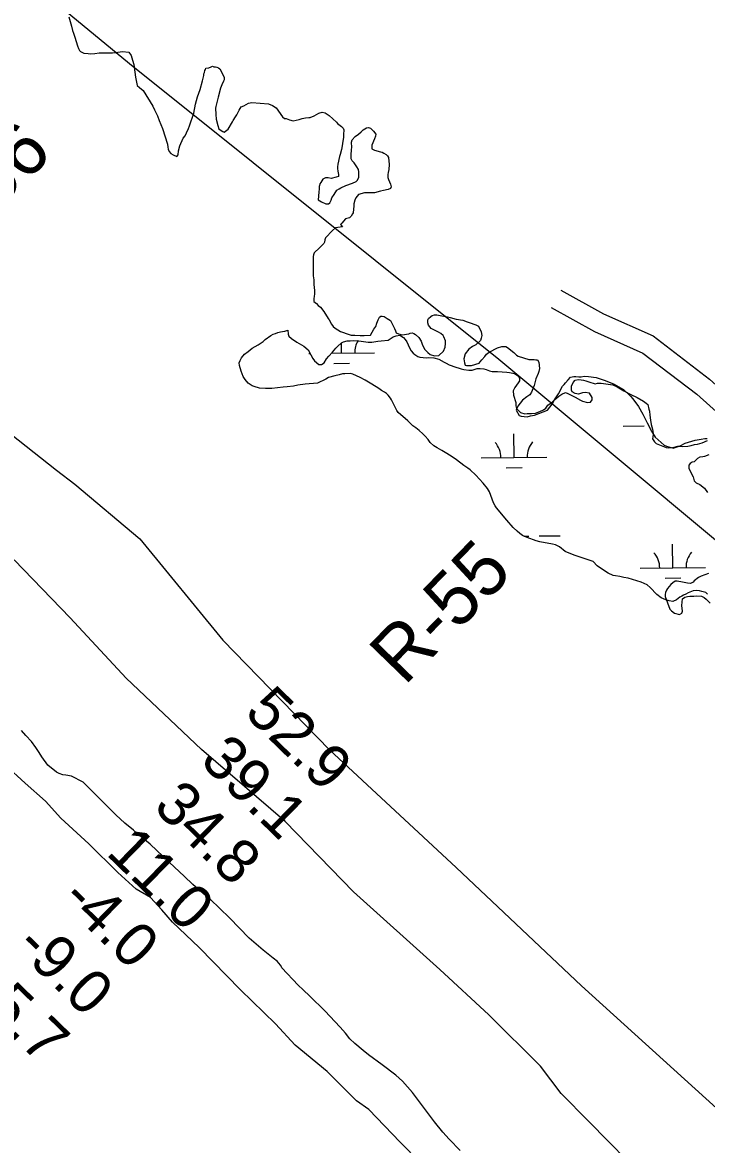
# Model space of a CAD drawing. Extents: x 3146026 to 3183936, y 897894 to 923344.
# Drawn here: x 3172319 to 3173362, y 912205 to 913917 of the extents above; entities that cross this region are included whole.
import ezdxf

# ---------------------------------------------------------------- set-up
doc = ezdxf.new("R2010")
doc.units = 0
for name, color, linetype in [('V-LEVE-TOET', 7, 'Continuous'), ('V-RIVR-EDGE', 7, 'Continuous'), ('V-RIVR-RANG', 7, 'Continuous'), ('V-RIVR-RANG-IDEN', 7, 'Continuous'), ('V-ROAD-CNTR', 7, 'Continuous'), ('V-SITE-VEGE', 7, 'Continuous'), ('V-TOPO-BNDY', 7, 'Continuous'), ('V-WETL-SWMP', 7, 'Continuous')]:
    doc.layers.add(name, color=color, linetype=linetype)

msp = doc.modelspace()

# ---------------------------------------------------------------- linework, layer by layer
at = {"layer": 'V-LEVE-TOET'}
for points in [[(3172100.1, 913448.3), (3172370.8, 913233.9), (3172398.7, 913212.6), (3172497.8, 913129.1), (3172624.4, 912974.6), (3172787.3, 912807.3), (3172980.7, 912627.4), (3173171.4, 912446.8), (3173377.7, 912260.1), (3173591.1, 912050.9), (3173767.1, 911895.3), (3173843.3, 911824.3), (3173892.6, 911768.4), (3173997.2, 911662.3), (3174154.9, 911518.6), (3174255.5, 911433.9), (3174348.6, 911370.2), (3174431.4, 911311.7), (3174516, 911243.3)], [(3173271.6, 912149.5), (3173183, 912239.6), (3173140.6, 912282.5), (3173109, 912324.3), (3173030.1, 912402.6), (3172955.5, 912472), (3172824.1, 912590.2), (3172719.5, 912697.6), (3172592.1, 912807.5), (3172477.4, 912916.6), (3172391.5, 913008.7), (3172306.5, 913097.3)]]:
    msp.add_lwpolyline(points, dxfattribs=at)
at = {"layer": 'V-RIVR-EDGE'}
msp.add_lwpolyline([(3172955.3, 912146.9), (3172895, 912208.4), (3172847.5, 912258), (3172828.6, 912271.4), (3172783.5, 912315.9), (3172735.1, 912356.2), (3172704.7, 912389), (3172651.7, 912440.9), (3172588.6, 912505.3), (3172548, 912544.2), (3172531.4, 912562.7), (3172514.4, 912581.6), (3172492.3, 912594.6), (3172464.6, 912620.1), (3172420.4, 912663.6), (3172377.5, 912703), (3172354, 912728.5), (3172323.1, 912756.2), (3172293.2, 912783.6)], dxfattribs=at)
at = {"layer": 'V-ROAD-CNTR'}
for points in [[(3173139.9, 913508.6), (3173205.1, 913472.4), (3173280.7, 913438.7), (3173366.6, 913372.9), (3173416.8, 913328), (3173469.6, 913282.3), (3173498.8, 913242.4), (3173574.6, 913161), (3173657.4, 913103.1), (3173709, 913080.7), (3173781.9, 913041.6), (3173863.9, 912987.1), (3173918.4, 912931.4), (3173981.3, 912871.8), (3174036.9, 912823), (3174086.6, 912783.4), (3174169.8, 912735.6), (3174248.5, 912696.9), (3174316.5, 912653.2), (3174389.2, 912593.3), (3174464.7, 912522.1), (3174535.7, 912475.2)], [(3173125.3, 913482.4), (3173191.7, 913445.6), (3173265.2, 913412.7), (3173347.4, 913349.8), (3173397, 913305.4), (3173447.4, 913261.8), (3173475.7, 913223.2), (3173554.8, 913138.2), (3173642.7, 913076.8), (3173695.9, 913053.6), (3173766.5, 913015.8), (3173844.7, 912963.9), (3173897.4, 912910), (3173961, 912849.6), (3174017.7, 912800), (3174069.7, 912758.5), (3174155.7, 912709.2), (3174233.7, 912670.7)]]:
    msp.add_lwpolyline(points, dxfattribs=at)
at = {"layer": 'V-SITE-VEGE'}
for points in [[(3172389.6, 913925.7), (3172392.8, 913915.2), (3172393.6, 913911.3), (3172395.5, 913905), (3172396.7, 913901.1), (3172399.1, 913894.9), (3172401, 913887.9), (3172403, 913881.6), (3172404.5, 913877.3), (3172406.1, 913874.6), (3172407.7, 913873), (3172412.4, 913870.3), (3172419, 913869.9), (3172422.9, 913869.5), (3172429.6, 913869.9), (3172436.2, 913871.1), (3172452.2, 913871.1), (3172456.5, 913870.8), (3172460.8, 913871.2), (3172468.2, 913872.3), (3172471.8, 913873.1), (3172481.1, 913872), (3172484.7, 913866.9), (3172487, 913859.9), (3172488.6, 913852.8), (3172490.6, 913841.5), (3172491.4, 913833.7), (3172493.7, 913821.2), (3172497.6, 913817.7), (3172503.1, 913813.4), (3172518, 913789.6), (3172520.4, 913783.8), (3172524.7, 913774.8), (3172527.4, 913767.4), (3172532.5, 913755.6), (3172540.4, 913731.4), (3172540.8, 913726.7), (3172541.2, 913724), (3172542.7, 913720.1), (3172545.5, 913717.4), (3172548.6, 913715.4), (3172554.5, 913712.7), (3172556.4, 913715.4), (3172556.8, 913721.3), (3172559.1, 913729.1), (3172564.2, 913740.5), (3172566.9, 913744.4), (3172569.2, 913748.7), (3172572, 913755.3), (3172573.9, 913759.6), (3172580.5, 913778.8), (3172582.8, 913792.5), (3172584.4, 913798.3), (3172586, 913803.8), (3172590.2, 913815.1), (3172593.7, 913828), (3172595.7, 913836.2), (3172595.7, 913839), (3172596.4, 913840.9), (3172597.2, 913843.7), (3172598, 913845.6), (3172598.8, 913847.2), (3172603.1, 913848), (3172607, 913849.5), (3172608.9, 913850.3), (3172610.9, 913849.5), (3172613.2, 913849.5), (3172615.6, 913849.2), (3172617.9, 913848), (3172619.9, 913846.4), (3172626.5, 913833.9), (3172626.5, 913829.6), (3172625.8, 913827.7), (3172623, 913822.2), (3172621.1, 913816.7), (3172617.6, 913803.1), (3172613.7, 913789), (3172613.3, 913786.3), (3172613.7, 913776.9), (3172614.5, 913769.5), (3172616.9, 913760.1), (3172618.5, 913755), (3172620.4, 913753.1), (3172624.7, 913750.7), (3172626.7, 913749.9), (3172632.9, 913754.6), (3172639.5, 913765.6), (3172640.3, 913767.6), (3172643.8, 913773.4)], [(3172643.8, 913773.4), (3172645.8, 913776.2), (3172649.3, 913783.6), (3172652.4, 913788.3), (3172656.7, 913790.2), (3172663.7, 913793.8), (3172668.8, 913794.9), (3172694.2, 913793), (3172700.1, 913790.3), (3172705.9, 913786.8), (3172715.7, 913773.2), (3172718.8, 913770.8), (3172721.2, 913770.4), (3172726.3, 913768.5), (3172731.7, 913767.3), (3172741.1, 913768.9), (3172745.4, 913770.5), (3172750.5, 913771.6), (3172755.6, 913772.4), (3172757.9, 913772.4), (3172763.8, 913774.8), (3172770.8, 913778.7), (3172775.9, 913780.3), (3172780.6, 913779.1), (3172786.8, 913775.2), (3172798.2, 913765.1), (3172799.7, 913763.1), (3172801.3, 913761.6), (3172805.6, 913758.5), (3172808.3, 913755.7), (3172809.1, 913753.4), (3172808.7, 913746.4), (3172808.7, 913741.7), (3172807.6, 913735.8), (3172806.8, 913728.8), (3172805.7, 913723.3), (3172803.7, 913715.9), (3172802.5, 913712.4), (3172799.8, 913701), (3172799.4, 913696.7), (3172799.5, 913694.4), (3172800.2, 913690.5), (3172801, 913685), (3172801, 913682.3), (3172797.5, 913681.1), (3172789.7, 913679.1), (3172785, 913679.9), (3172781.1, 913679.9), (3172777.2, 913677.9), (3172774.1, 913672.8), (3172772.5, 913670.9), (3172772.2, 913668.5), (3172771.4, 913666.6), (3172771.4, 913663.5), (3172771, 913658), (3172769.8, 913646.3), (3172774.9, 913643.2), (3172781.6, 913640.4), (3172785.9, 913640.4), (3172787.8, 913642), (3172789.8, 913645.9), (3172790.9, 913649.4), (3172794.4, 913654.5), (3172798.3, 913661.2), (3172801.9, 913663.5), (3172804.6, 913664.7), (3172812.4, 913668.6), (3172822.5, 913672.1), (3172828, 913674.5), (3172829.6, 913676.1), (3172831.9, 913680.4), (3172831.9, 913689.4), (3172831.5, 913692.9), (3172829.1, 913696.8), (3172824.8, 913703), (3172821.7, 913706.1), (3172820.5, 913709.3), (3172820.5, 913717.1), (3172820.9, 913721), (3172820.9, 913723.3), (3172821.3, 913726.5), (3172820.9, 913734.3), (3172821.6, 913738.2), (3172826.3, 913743.3), (3172831.4, 913746.8), (3172835.7, 913750.3), (3172838.4, 913753.4), (3172843.9, 913756.6), (3172846.6, 913757), (3172849.7, 913755.8), (3172854.4, 913751.5), (3172858, 913746.8), (3172857.6, 913743.7), (3172856, 913739.8), (3172851.7, 913730), (3172851.8, 913724.5), (3172855.7, 913722.2), (3172865, 913719.9), (3172867.4, 913719.1), (3172870.1, 913717.9), (3172873.6, 913715.6)], [(3172873.6, 913715.6), (3172875.6, 913713.7), (3172877.2, 913710.9), (3172878.4, 913700.4), (3172877.6, 913692.9), (3172876.8, 913688.3), (3172876, 913685.1), (3172876.4, 913680.8), (3172877.2, 913677.7), (3172880.4, 913670.3), (3172881.5, 913666.4), (3172880.4, 913663.7), (3172876.9, 913662.5), (3172869.8, 913660.5), (3172865.1, 913659.7), (3172855.8, 913657.4), (3172840.9, 913657.3), (3172831.6, 913654.6), (3172827.3, 913649.5), (3172825.7, 913646), (3172824.5, 913640.5), (3172824.6, 913637.4), (3172823.4, 913626.8), (3172822.6, 913624.9), (3172820.3, 913621.4), (3172817.9, 913619), (3172813.6, 913618.2), (3172811.7, 913617.4), (3172806.2, 913610.8), (3172804.3, 913608.8), (3172807.3, 913605.5), (3172796.5, 913603.7), (3172791.8, 913599.8), (3172781.3, 913588.5), (3172780.1, 913585.7), (3172779.7, 913581.8), (3172778.6, 913579.9), (3172771.9, 913573.2), (3172763.7, 913565.4), (3172763, 913562.7), (3172762.6, 913559.9), (3172762.6, 913530.6), (3172763.4, 913524.4), (3172763.4, 913517.3), (3172764.6, 913508), (3172764.6, 913502.1), (3172763.8, 913500.1), (3172763.5, 913494.7), (3172763.5, 913491.2), (3172767.4, 913488.4), (3172770.1, 913485.3), (3172773.3, 913482.6), (3172778.7, 913476), (3172785, 913465.4), (3172786.6, 913463.1), (3172790.1, 913456.8), (3172792.8, 913453.3), (3172796, 913450.6), (3172803.8, 913445.5), (3172817.1, 913440.9), (3172820.2, 913440.1), (3172826.1, 913440.1), (3172834.3, 913439.3), (3172840.1, 913439.3), (3172849.9, 913440.1), (3172855, 913449.1), (3172857.7, 913453.4), (3172859.6, 913458.1), (3172861.6, 913463.6), (3172863.5, 913467.5), (3172865.5, 913468.7), (3172867.8, 913468.7), (3172870.6, 913468.3), (3172875.2, 913465.6), (3172880.3, 913462.1), (3172886.6, 913450), (3172887.8, 913446.4), (3172889, 913443.7), (3172892.5, 913441.8), (3172898, 913440.6), (3172908.1, 913441.8), (3172910.5, 913443), (3172913.2, 913443.4), (3172915.9, 913442.6), (3172918.3, 913441), (3172923.7, 913436.4), (3172926.9, 913430.9), (3172928.8, 913426.2), (3172929.6, 913423.5), (3172932.8, 913418), (3172937.1, 913413.3), (3172940.6, 913410.2), (3172947.2, 913408.3), (3172953.9, 913409.1), (3172960.9, 913415.3), (3172963.6, 913421.6), (3172964.4, 913427.4), (3172964.4, 913431.3), (3172961.6, 913437.6), (3172960.5, 913439.5), (3172956.9, 913442.3)], [(3172956.9, 913442.3), (3172953.4, 913444.6), (3172942.1, 913450.1), (3172938.2, 913455.1), (3172937, 913459), (3172937.4, 913463.3), (3172938.5, 913465.3), (3172941.7, 913468.4), (3172944, 913470), (3172947.5, 913471.2), (3172951, 913471.2), (3172958.8, 913469.2), (3172967.4, 913468.1), (3172971.4, 913466.9), (3172980.7, 913464.6), (3172990.5, 913462.6), (3172997.2, 913460.3), (3173000.3, 913459.5), (3173010.4, 913455.6), (3173014.7, 913453.7), (3173018.7, 913445.1), (3173019.5, 913439.3), (3173018.7, 913435.3), (3173017.5, 913431.8), (3173010.5, 913425.2), (3173005.4, 913422.4), (3173000, 913418.5), (3172994.1, 913411.5), (3172992.2, 913403.7), (3172993, 913397.8), (3172994.1, 913394.3), (3172996.1, 913393.5), (3173003.9, 913393.5), (3173015.6, 913397.4), (3173017.2, 913399), (3173019.5, 913402.1), (3173024.2, 913407.6), (3173026.9, 913411.1), (3173030.8, 913413.9), (3173043.7, 913420.5), (3173050.3, 913422.5), (3173056.2, 913422.5), (3173058.9, 913421), (3173068.3, 913413.6), (3173072.6, 913409.3), (3173075, 913408.1), (3173083.2, 913405.4), (3173091.4, 913403), (3173099.6, 913402.7), (3173102, 913402.3), (3173104.3, 913402.3), (3173106.6, 913398.8), (3173107.4, 913389), (3173106.7, 913384.7), (3173105.5, 913381.2), (3173102, 913373.4), (3173099.3, 913363.2), (3173095.4, 913353), (3173092.7, 913348.7), (3173088, 913346), (3173081.4, 913340.9), (3173074.7, 913331.5), (3173072, 913325.3), (3173076.3, 913317.1), (3173079.4, 913316.3), (3173088.8, 913315.5), (3173093.9, 913316.7), (3173100.1, 913317.9), (3173106.8, 913320.2), (3173119.7, 913325.3), (3173126.7, 913334.7), (3173130.6, 913341.4), (3173136.4, 913350.4), (3173142.7, 913362.1), (3173145, 913364.8), (3173147.3, 913367.2), (3173151.2, 913371.9), (3173154.7, 913375.8), (3173159.8, 913377), (3173162.9, 913377), (3173167.6, 913376.2), (3173171.1, 913376.6), (3173175.8, 913377.4), (3173182.1, 913377), (3173193.8, 913375.5), (3173207.5, 913370.8), (3173221.2, 913365.4), (3173235.6, 913356.8), (3173246.2, 913346.7), (3173249.7, 913342.8), (3173258.4, 913331.1), (3173265, 913319.3), (3173271.7, 913306.1), (3173278.3, 913293.6), (3173283.8, 913284.2), (3173297.9, 913272.1), (3173301.4, 913270.6), (3173312, 913267.5), (3173314.7, 913268.3), (3173322.1, 913271), (3173329.9, 913274.9)], [(3173329.9, 913274.9), (3173345.2, 913279.6), (3173354.2, 913281.2), (3173359.6, 913282), (3173363.5, 913282)], [(3173365.9, 913257.4), (3173359.3, 913255), (3173356.5, 913254.3), (3173352.2, 913253.5), (3173348.7, 913251.5), (3173343.3, 913246.8), (3173340.5, 913246), (3173337.4, 913244.1), (3173335.1, 913241.3), (3173335.5, 913237), (3173338.2, 913230.4), (3173341.7, 913223.8), (3173342.5, 913221.8), (3173343.7, 913217.5), (3173346.5, 913214.8), (3173351.9, 913212.1), (3173359.4, 913206.6), (3173363.7, 913200)], [(3173365.4, 913076.1), (3173354.1, 913072.2), (3173350.2, 913070.2), (3173343.6, 913064.8), (3173342, 913062.8), (3173338.1, 913060.8), (3173333.4, 913061.2), (3173325.6, 913063.2), (3173317.4, 913064.7), (3173314.7, 913064.7), (3173310.8, 913062), (3173308, 913059.6), (3173302.6, 913053.4), (3173301.4, 913051), (3173299.9, 913047.1), (3173299.1, 913044), (3173299.1, 913041.2), (3173306.5, 913021.7), (3173308.9, 913019), (3173313.6, 913015.5), (3173321, 913013.5), (3173324.9, 913015.5), (3173325.7, 913018.6), (3173324.9, 913027.2), (3173325.7, 913037.4), (3173329.2, 913040.1), (3173333.1, 913041.3), (3173336.6, 913041.7), (3173342.8, 913041.7), (3173347.1, 913042.1), (3173354.6, 913041.7), (3173358.5, 913039.8), (3173361.6, 913037), (3173367.9, 913030.8)], [(3172746.9, 912440.6), (3172739.5, 912448), (3172714.8, 912474.5), (3172712.9, 912478), (3172709.7, 912481.9), (3172707.8, 912483.9), (3172701.5, 912489.3), (3172686.3, 912501.4), (3172664.7, 912519.4), (3172634.6, 912550.6), (3172605.3, 912579), (3172594.7, 912587.6), (3172583, 912597.8), (3172579, 912601.7), (3172565.7, 912614.1), (3172543, 912635.2), (3172513.7, 912662.9), (3172497.7, 912676.1), (3172488.3, 912684.3), (3172475.3, 912695.2), (3172461.3, 912708.1), (3172444.4, 912724.9), (3172440.9, 912728), (3172434.3, 912734.6), (3172424.1, 912745.2), (3172411.6, 912757.6), (3172393.6, 912767), (3172385, 912768.5), (3172380.7, 912768.9), (3172375.2, 912770.9), (3172370.9, 912773.2), (3172357.6, 912783.7), (3172348.6, 912796.2), (3172344.3, 912802.8), (3172339.6, 912810.6), (3172332.9, 912819.6), (3172324.3, 912829), (3172317.7, 912836.8)], [(3172986.8, 912195.7), (3172969.6, 912212.8), (3172960.2, 912223.3), (3172947.3, 912239.3), (3172914, 912284.2), (3172898.7, 912301.4), (3172888.2, 912310.7), (3172867.4, 912326.3), (3172846.7, 912341.5), (3172838.5, 912348.2), (3172826, 912358.7), (3172818.5, 912366.1), (3172811.5, 912374.7), (3172803.3, 912384), (3172780.2, 912408.6), (3172757.5, 912431.2), (3172746.9, 912440.6)]]:
    msp.add_lwpolyline(points, dxfattribs=at)
at = {"layer": 'V-TOPO-BNDY'}
msp.add_lwpolyline([(3176856.6, 910386.2), (3176814.3, 910437.3), (3176728.4, 910587.3), (3176643.2, 910736.9), (3176419.3, 910929.6), (3176094.5, 911180.9), (3175633.9, 911415.2), (3175249.7, 911621.4), (3174883.6, 911879.4), (3174485.2, 912144.9), (3174133.9, 912423.2), (3173763.7, 912766.5), (3173388.4, 913116.7), (3173045.4, 913402.9), (3172482.4, 913854.3), (3172147.4, 914130.1)], dxfattribs=at)
at = {"layer": 'V-WETL-SWMP'}
for p, q in [((3172805.7, 913412.4), (3172805.6, 913427.9)), ((3172755.8, 913411.9), (3172757.8, 913412)), ((3172790.3, 913412.3), (3172855.7, 913412.9)), ((3172793.9, 913396.9), (3172817.9, 913397.1)), ((3173068.8, 913253.2), (3173068.4, 913289.2)), ((3173235.4, 913301.3), (3173267.4, 913301.6)), ((3173018.8, 913252.7), (3173118.8, 913253.7)), ((3173056.9, 913237.6), (3173080.9, 913237.9)), ((3173083.8, 913133.3), (3173091.1, 913133.3)), ((3173107.1, 913133.5), (3173139.1, 913133.8)), ((3173310.9, 913084.8), (3173310.6, 913120.8)), ((3173261, 913084.3), (3173360.9, 913085.3)), ((3173299.1, 913069.2), (3173323.1, 913069.5))]:
    msp.add_line(p, q, dxfattribs=at)
for points in [[(3172881.9, 913341), (3172880.2, 913343.8), (3172876.6, 913348.5), (3172874, 913351.1), (3172871.3, 913353.1), (3172866.6, 913355.7), (3172862.5, 913358.6), (3172851.8, 913365.3), (3172841.5, 913371.3), (3172833.8, 913375.2), (3172822.9, 913380.2), (3172818.6, 913381.3), (3172810.6, 913381.1), (3172807, 913380.8), (3172801.8, 913379.3), (3172795.4, 913377.7), (3172786, 913375.1), (3172781.7, 913372.7), (3172769, 913366.8), (3172750, 913365.3), (3172739.2, 913363.6), (3172732.2, 913362.3), (3172722.5, 913361.1), (3172716.5, 913360.7), (3172699.5, 913358.6), (3172689.9, 913358.3), (3172680.7, 913359.2), (3172672.5, 913361.4), (3172669.5, 913362.7), (3172663.3, 913366.8), (3172658.6, 913372.3), (3172655.6, 913377.1), (3172652.4, 913385.2), (3172650.1, 913393.8), (3172649.5, 913397.5), (3172651, 913401.1), (3172653.1, 913405.1), (3172657.6, 913410.7), (3172663.2, 913415.2), (3172669.5, 913419.9), (3172678.3, 913425.3), (3172686, 913430.4), (3172689.4, 913433.4), (3172698, 913439.6), (3172701.6, 913441.5), (3172704.7, 913442.4), (3172708.5, 913443.9), (3172712.6, 913445.1), (3172715.6, 913445.5), (3172719, 913446), (3172722.4, 913447), (3172723.8, 913447.5), (3172724, 913441.5), (3172725.5, 913438.4), (3172729.1, 913434.7), (3172737.3, 913429.2), (3172748.1, 913423), (3172754.5, 913417.7), (3172759, 913409.7), (3172761.9, 913404.2), (3172764.3, 913400.9), (3172771.2, 913395.2), (3172774.9, 913395.4), (3172778.9, 913397.6), (3172782.7, 913403.6), (3172786.2, 913408), (3172791.9, 913414), (3172797, 913420.2), (3172799.4, 913422.6), (3172805.6, 913428), (3172808.7, 913429.7), (3172814.2, 913431.1), (3172818.7, 913431.5), (3172823.8, 913431.8), (3172831.9, 913431.5), (3172842.8, 913430), (3172846.1, 913429.4), (3172851.9, 913429.1), (3172860.9, 913430.9), (3172866, 913431.2), (3172876.6, 913432.3), (3172884.4, 913437.6), (3172889, 913438.9), (3172894.7, 913439.8), (3172900.3, 913436.3), (3172902.9, 913433.4), (3172905.4, 913429.7), (3172909.2, 913420.4), (3172912, 913415.8), (3172914.7, 913412.7), (3172917.6, 913410.5), (3172922.2, 913407.6), (3172925.3, 913406.3), (3172935.1, 913405.6), (3172938.4, 913405.8), (3172946.6, 913405.6), (3172954.1, 913403.2), (3172962.1, 913398.8), (3172965.4, 913397.3), (3172969.8, 913394.8), (3172972.9, 913393.5)], [(3172972.9, 913393.5), (3172976.9, 913392), (3172988, 913388.5), (3172992.4, 913387.4), (3172999.7, 913386.7), (3173004.8, 913386.7), (3173009.6, 913388.3), (3173012.7, 913388.9), (3173017.2, 913389), (3173022.5, 913388.7), (3173026.2, 913387.6), (3173031.5, 913385.4), (3173035.3, 913384.3), (3173043.5, 913384.6), (3173057.6, 913383.5), (3173061.6, 913383.1), (3173066.9, 913382), (3173070.5, 913380.9), (3173075.3, 913377.3), (3173077.3, 913373.6), (3173077.3, 913370), (3173075.1, 913367.4), (3173070.1, 913360.1), (3173067.6, 913354.8), (3173067.9, 913348.3), (3173071.4, 913337.1), (3173071.7, 913332), (3173072.3, 913328), (3173078.5, 913321.8), (3173085.2, 913320.1), (3173088.9, 913320.5), (3173095.4, 913320.5), (3173101.5, 913321), (3173108, 913323.2), (3173113.7, 913325.9), (3173117, 913328.7), (3173120.5, 913332.9), (3173126.7, 913337.8), (3173130.9, 913341.8), (3173136.9, 913346.7), (3173141.5, 913349.8), (3173147.1, 913352.5), (3173151, 913350.9), (3173162.1, 913345.4), (3173169.9, 913340.8), (3173173.4, 913339.2), (3173180.7, 913337), (3173185.1, 913337.5), (3173188, 913341.5), (3173188, 913344.6), (3173183.6, 913351.4), (3173177.1, 913352.5), (3173173.2, 913351.8), (3173167.2, 913350.1), (3173162.1, 913350.7), (3173157.2, 913353.4), (3173156.3, 913356.2), (3173156.3, 913362), (3173159, 913367.7), (3173161.8, 913371.3), (3173166.3, 913372.2), (3173171.1, 913372), (3173174.9, 913371.1), (3173178.2, 913370), (3173182.9, 913368.9), (3173192.6, 913365.8), (3173195.9, 913366.7), (3173201.7, 913366.5), (3173219.4, 913363.9), (3173226.2, 913361), (3173236.4, 913355), (3173247, 913349.3), (3173256.6, 913344.9), (3173266.1, 913339.2), (3173270.3, 913336.3), (3173272.7, 913333.9), (3173274.3, 913326.8), (3173275.2, 913323.9), (3173275.6, 913318), (3173277, 913310.2), (3173277.9, 913303.8), (3173279.9, 913296.7), (3173280.5, 913293.4), (3173280.8, 913289), (3173280.5, 913284.8), (3173280.1, 913281.7), (3173283.2, 913277.3), (3173285.7, 913274.6), (3173290.7, 913272.4), (3173300.9, 913268.7), (3173304.9, 913268), (3173310.9, 913268.7), (3173318.8, 913270.5), (3173322.2, 913270.5), (3173326.4, 913270), (3173333.9, 913270.3), (3173339, 913271.6), (3173344, 913273.2), (3173348.3, 913273.6), (3173355.8, 913275.6), (3173363.7, 913279.2)], [(3173363.9, 913044.9), (3173361.1, 913047.3), (3173355.2, 913048.8), (3173351.5, 913049.6), (3173346.6, 913050.1), (3173341.7, 913049.9), (3173334.1, 913046.7), (3173330.9, 913044.9), (3173327.3, 913043.3), (3173324.5, 913041.8), (3173321.7, 913040), (3173316.5, 913035.8), (3173311, 913033.6), (3173305.2, 913034.7), (3173300.5, 913035.8), (3173293.2, 913039), (3173286.3, 913044), (3173276.5, 913054.9), (3173271.8, 913058.8), (3173262.8, 913062.9), (3173242.9, 913069.1), (3173236, 913070.2), (3173230, 913071.5), (3173223.4, 913072.4), (3173219.9, 913073.3), (3173212.4, 913076.9), (3173202.2, 913083.2), (3173195.7, 913088.1), (3173189.5, 913094.5), (3173180.5, 913097.6), (3173168.1, 913101.4), (3173160.4, 913104.2), (3173146.9, 913109.9), (3173137.9, 913117.1), (3173131.9, 913119.7), (3173127.4, 913121), (3173107.9, 913124.5), (3173102.3, 913126), (3173088.6, 913131), (3173081.4, 913134.4), (3173077.5, 913137.2), (3173073.6, 913140.6), (3173067.6, 913146.5), (3173057.8, 913157.4), (3173042, 913176.5), (3173040.1, 913179.5), (3173037.5, 913184.2), (3173031.5, 913201), (3173028.3, 913205.7), (3173021.5, 913214.1), (3173010.3, 913226.3), (3173001.8, 913234.2), (3172998.2, 913237), (3172992.4, 913241.1), (3172981.2, 913249.5), (3172972.9, 913255.1), (3172963.9, 913260.7), (3172958.6, 913263.9), (3172951.7, 913267.8), (3172946.3, 913271.2), (3172941, 913276.2), (3172937.6, 913280.7), (3172933.3, 913285.8), (3172929.7, 913289.3), (3172924.1, 913294.2), (3172918.7, 913298.5), (3172914.3, 913301.5), (3172906.5, 913309.1), (3172891.8, 913322.1), (3172889.9, 913324.9), (3172887.7, 913328.8), (3172881.9, 913341)]]:
    msp.add_lwpolyline(points, dxfattribs=at)
for centre, start, end in [((3172861, 913413.5), 149.0643, 181.3429), ((3173013.5, 913253.1), 359.7992, 41.3429), ((3173124, 913254.2), 139.7992, 181.3429), ((3173255.7, 913084.7), 359.7992, 41.3429), ((3173366.2, 913085.8), 139.7992, 181.3429)]:
    msp.add_arc(centre, 35.2, start, end, dxfattribs=at)

# ---------------------------------------------------------------- texts
at = {"layer": 'V-RIVR-RANG'}
for s, p in [('52.9', (3172655.6, 912861.8)), ('39.1', (3172587.9, 912788.1)), ('34.8', (3172516.6, 912718)), ('11.0', (3172445, 912648.2)), ('-4.0', (3172375.4, 912576.3)), ('-9.0', (3172305.8, 912504.5)), ('-5.7', (3172238.3, 912430.7))]:
    msp.add_text(s, height=67, rotation=315.7683, dxfattribs=at).set_placement(p)
at = {"layer": 'V-RIVR-RANG-IDEN'}
for s, rotation, p in [('R-56', 44.0839, (3172194.2, 913547.6)), ('R-55', 45.9115, (3172901.5, 912903.5))]:
    msp.add_text(s, height=83, rotation=rotation, dxfattribs=at).set_placement(p)

doc.saveas('drawing.dxf')
